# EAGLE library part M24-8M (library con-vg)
CONNECTOR male, 24 pins + 8 coax type C, rows ABC, grid 2.54 mm
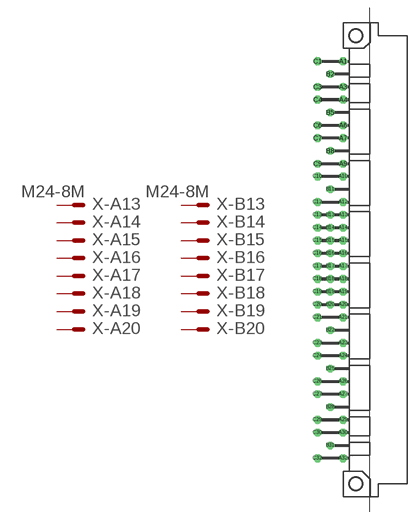
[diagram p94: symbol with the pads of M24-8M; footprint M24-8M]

Designator prefix X; gates -A13=MVAL -A14=MAL -A15=MAL -A16=MAL -A17=MAL -A18=MAL -A19=MAL -A20=MAL -B13=MVAL -B14=MAL -B15=MAL -B16=MAL -B17=MAL -B18=MAL -B19=MAL -B20=MAL -C13=MVAL -C14=MAL -C15=MAL -C16=MAL -C17=MAL -C18=MAL -C19=MAL -C20=MAL -1=COAX -2=COAX -3=COAX -4=COAX -5=COAX -6=COAX -7=COAX -8=COAX

## M24-8M  [M24-8M]
A1  -1:S1  pas
A3  -1:S2  pas
A4  -2:S1  pas
A6  -2:S2  pas
A7  -3:S1  pas
A9  -3:S2  pas
A10  -4:S1  pas
A12  -4:S2  pas
A13  -A13:S  pas
A14  -A14:S  pas
A15  -A15:S  pas
A16  -A16:S  pas
A17  -A17:S  pas
A18  -A18:S  pas
A19  -A19:S  pas
A20  -A20:S  pas
A21  -5:S1  pas
A23  -5:S2  pas
A24  -6:S1  pas
A26  -6:S2  pas
A27  -7:S1  pas
A29  -7:S2  pas
A30  -8:S1  pas
A32  -8:S2  pas
B2  -1:S  pas
B5  -2:S  pas
B8  -3:S  pas
B11  -4:S  pas
B13  -B13:S  pas
B14  -B14:S  pas
B15  -B15:S  pas
B16  -B16:S  pas
B17  -B17:S  pas
B18  -B18:S  pas
B19  -B19:S  pas
B20  -B20:S  pas
B22  -5:S  pas
B25  -6:S  pas
B28  -7:S  pas
B31  -8:S  pas
C1  -1:S3  pas
C3  -1:S4  pas
C4  -2:S3  pas
C6  -2:S4  pas
C7  -3:S3  pas
C9  -3:S4  pas
C10  -4:S3  pas
C12  -4:S4  pas
C13  -C13:S  pas
C14  -C14:S  pas
C15  -C15:S  pas
C16  -C16:S  pas
C17  -C17:S  pas
C18  -C18:S  pas
C19  -C19:S  pas
C20  -C20:S  pas
C21  -5:S3  pas
C23  -5:S4  pas
C24  -6:S3  pas
C26  -6:S4  pas
C27  -7:S3  pas
C29  -7:S4  pas
C30  -8:S3  pas
C32  -8:S4  pas

## Footprint M24-8M (pad centres in mm)
CONNECTOR male, 24 pins + 8 coax type C, rows ABC, grid 2.54 mm
drill 1.016 octagon: A1 -2.54,39.37; A3 -2.54,34.29; A4 -2.54,31.75; A6 -2.54,26.67; A7 -2.54,24.13; A9 -2.54,19.05; A10 -2.54,16.51; A12 -2.54,11.43; A13 -2.54,8.89; A14 -2.54,6.35; A15 -2.54,3.81; A16 -2.54,1.27; A17 -2.54,-1.27; A18 -2.54,-3.81; A19 -2.54,-6.35; A20 -2.54,-8.89; A21 -2.54,-11.43; A23 -2.54,-16.51; A24 -2.54,-19.05; A26 -2.54,-24.13; A27 -2.54,-26.67; A29 -2.54,-31.75; A30 -2.54,-34.29; A32 -2.54,-39.37; B2 -5.08,36.83; B5 -5.08,29.21; B8 -5.08,21.59; B11 -5.08,13.97; B13 -5.08,8.89; B14 -5.08,6.35; B15 -5.08,3.81; B16 -5.08,1.27; B17 -5.08,-1.27; B18 -5.08,-3.81; B19 -5.08,-6.35; B20 -5.08,-8.89; B22 -5.08,-13.97; B25 -5.08,-21.59; B28 -5.08,-29.21; B31 -5.08,-36.83; C1 -7.62,39.37; C3 -7.62,34.29; C4 -7.62,31.75; C6 -7.62,26.67; C7 -7.62,24.13; C9 -7.62,19.05; C10 -7.62,16.51; C12 -7.62,11.43; C13 -7.62,8.89; C14 -7.62,6.35; C15 -7.62,3.81; C16 -7.62,1.27; C17 -7.62,-1.27; C18 -7.62,-3.81; C19 -7.62,-6.35; C20 -7.62,-8.89; C21 -7.62,-11.43; C23 -7.62,-16.51; C24 -7.62,-19.05; C26 -7.62,-24.13; C27 -7.62,-26.67; C29 -7.62,-31.75; C30 -7.62,-34.29; C32 -7.62,-39.37
hole 2.8 at 0,44.45
hole 2.8 at 0,-44.45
